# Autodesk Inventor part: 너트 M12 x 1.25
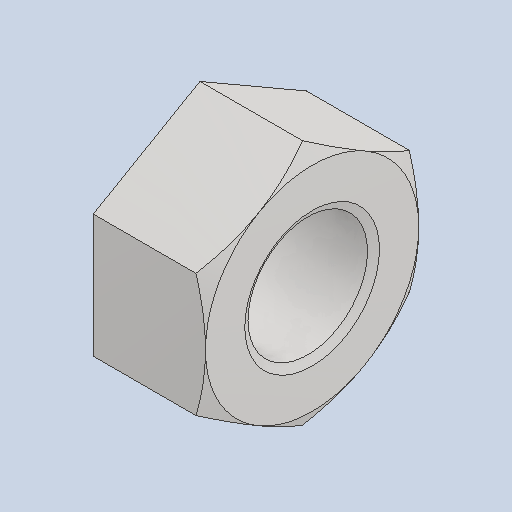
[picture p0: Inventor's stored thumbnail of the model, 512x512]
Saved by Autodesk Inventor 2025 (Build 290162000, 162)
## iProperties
Created: 2025-08
Part Number: 너트 M12 x 1.25
Material: 스테인리스강
Description: 6각 너트
Document SubType Name: Modeling
Designer: infra04
Density: 8.08 g/cm^3
Appearance: 기본값
Author: jhkim
Sending System: Autodesk Inventor 2026
Preprocessor: ST-DEVELOPER v20.1
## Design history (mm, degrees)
feature "Solid1"
node "솔리드1"
